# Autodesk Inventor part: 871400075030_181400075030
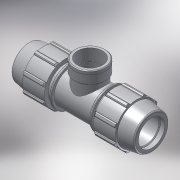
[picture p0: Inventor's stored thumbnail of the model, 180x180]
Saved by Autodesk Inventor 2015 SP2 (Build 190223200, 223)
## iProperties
Created: 2017-02
Part Number: 871400075030_181400075030
Material: PVC-Piping
Description: PLASSON TEE WITH THREADED FEMALE OFFTAKE 75-3"-75
Document SubType Name: Modeling
Designer: KIM
Mass: 92.6774 g
Surface Area: 199.44 cm^2
Volume: 66.1981 cm^3
Density: 1.4 g/cm^3
Appearance: Smooth - White
Author: KIM
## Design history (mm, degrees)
derived "87140.ipt"
feature "Solid1::87140.ipt"
feature "Solid2::87140.ipt"
tag "TaggingFeature1"
body "Solid1"
other parameters: "d2" = 75, "d4" = 15.41667, "d5" = 44.4, "d7" = 132, "d11" = 6.16667, "d13" = 120 deg, "d14" = 97.5, "d15" = 12 deg, "d16" = 114.84, "d18" = 3.75, "d19" = 35 deg, "d20" = 17.5 deg, "d21" = 122.76, "d23" = 0, "d25" = 360 deg, "d27" = 2.64, "d33" = 1.5, "d42" = 66.6, "d43" = 3.96, "d46" = 2.25, "d68" = 11.1, "d76" = 84.926, "d80" = 2.54778, "d91" = 99, "d93" = 137, "d95" = 67.5, "d112" = 36, "d115" = 106.1575, "d116" = 135 deg, "d117" = 97.6649, "d119" = 67.5, "d121" = 0, "d122" = 67.5, "d124" = 0, "d128" = 0, "d129" = 7.5, "d130" = 10.8, "d131" = 0.3, "d132" = 0.3, "d133" = 106.1575, "d_" = 75, "E_" = 132, "l_" = 137, "l_2" = 36, "Rp_" = 84.926
